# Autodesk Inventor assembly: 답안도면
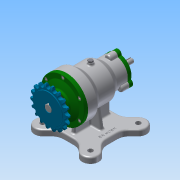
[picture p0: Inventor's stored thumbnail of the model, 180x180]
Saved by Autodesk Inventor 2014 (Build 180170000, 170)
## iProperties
Created: 2017-03
Part Number: 답안도면
Document SubType Name: Assembly
Designer: NET
Author: NET
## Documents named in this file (14)
- C:\Users\NET\Desktop\470307V1007\답안도면.iam
- C:\Users\NET\Desktop\470307V1007\본체.ipt
- C:\Users\NET\Desktop\470307V1007\축.ipt
- C:\Users\NET\Desktop\470307V1007\베어링-6203.ipt
- C:\Users\NET\Desktop\470307V1007\앞커버.ipt
- C:\Users\NET\Desktop\470307V1007\베어링-6200.ipt
- C:\Users\NET\Desktop\470307V1007\뒤커버.ipt
- C:\Users\NET\Desktop\470307V1007\오일 실 17 30 8.ipt
- C:\Users\NET\Desktop\470307V1007\오일 실 10 20 7.ipt
- C:\Users\NET\Desktop\470307V1007\키5x5.ipt
- C:\Users\NET\Desktop\470307V1007\스프로킷.ipt
- C:\Users\NET\Desktop\470307V1007\볼트 M5 x 10.ipt
- 볼트 M5 x 10.ipt
- C:\Users\NET\Desktop\470307V1007\볼트 M4 x 12.ipt
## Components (10 placed, 1 different names)
1. ISO 4762 M4 x 12:1
2. ISO 4762 M4 x 12:3
3. ISO 4762 M4 x 12:4
4. ISO 4762 M4 x 12:5
5. ISO 4762 M4 x 12:6
6. ISO 4762 M4 x 12:7
7. ISO 4762 M4 x 12:2
8. ISO 4762 M4 x 12:8
9. ISO 4762 M4 x 12:9
10. ISO 4762 M4 x 12:10
